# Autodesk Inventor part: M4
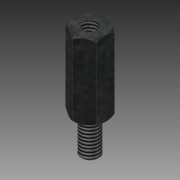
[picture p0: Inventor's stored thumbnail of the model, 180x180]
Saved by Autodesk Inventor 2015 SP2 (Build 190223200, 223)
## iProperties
Created: 2012-08
Part Number: M4
Material: Stahl
Document SubType Name: Modeling
Designer: rYan
Density: 7.85 g/cm^3
Mass: 1.74537 g
Surface Area: 3.04272 cm^2
Volume: 0.22234 cm^3
Appearance: Platte
Author: rYan
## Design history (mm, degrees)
derived "Abstandsbolzen Typ B.ipt"
feature "Volumenkörper1::Abstandsbolzen Typ B.ipt"
tag "Bezeichnung1"
node "Volumenkörper1"
other parameters: "SW" = 7, "L" = 17, "d2" = 0, "l_" = 9, "d9" = 118 deg, "GA_" = 4, "A_" = 8, "d13" = 0, "d17" = 0.25, "d20" = 45 deg
